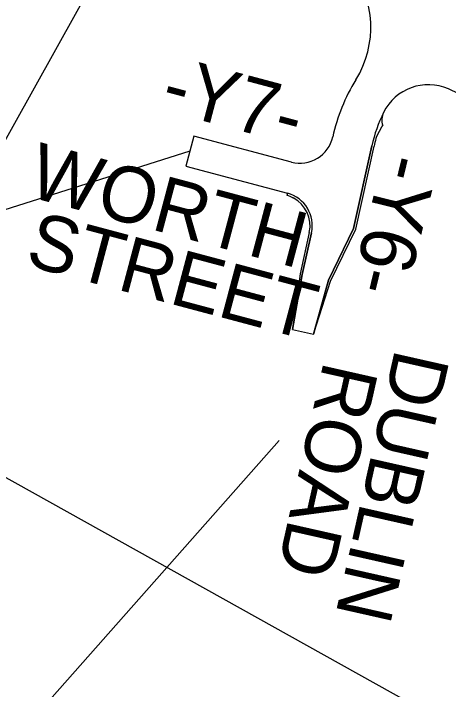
# Model space of a CAD drawing. Extents: x 1754939 to 1770240, y 706534 to 717510.
# Drawn here: x 1763770 to 1764161, y 710711 to 711317 of the extents above; entities that cross this region are included whole.
import ezdxf

# ---------------------------------------------------------------- set-up
doc = ezdxf.new("R2010")
doc.units = 0
for name, color, linetype in [('ENG SEALS CELL', 7, 'Continuous'), ('Prop Lane Arrow CELL', 7, 'Continuous'), ('Prop SS Cut Line', 7, 'Continuous'), ('Sheet PE Seal Cell', 7, 'Continuous')]:
    doc.layers.add(name, color=color, linetype=linetype)

msp = doc.modelspace()

# ---------------------------------------------------------------- linework, layer by layer
at = {"layer": 'ENG SEALS CELL'}
msp.add_lwpolyline([(1763634.1949825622, 710972.3161103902), (1763634.1949825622, 710972.3161103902), (1763865.6585117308, 711387.9613402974), (1764374.3315787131, 711761.9610198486), (1765360.9096948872, 711212.5534788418), (1765258.0264943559, 711027.8033728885), (1764850.0689356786, 710295.2231090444)], close=True, dxfattribs=at)
at = {"layer": 'Prop Lane Arrow CELL'}
for p, q in [((1764101.5980315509, 711216.4287330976), (1764101.5965902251, 711216.4250910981)), ((1764101.5965902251, 711216.4250910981), (1764101.5980315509, 711216.4287330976)), ((1763931.965230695, 711206.8954704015), (1763924.7579165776, 711179.8389624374)), ((1764019.687593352, 711183.5279824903), (1763931.965230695, 711206.8954704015)), ((1764075.378798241, 711123.8104545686), (1764091.8260664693, 711198.1455051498)), ((1764091.8260664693, 711198.1455051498), (1764075.378798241, 711123.8104545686)), ((1764077.3315700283, 711123.378387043), (1764093.7788382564, 711197.7134376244)), ((1763924.7579165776, 711179.8389624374), (1764016.1035829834, 711155.5062986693)), ((1764016.1035829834, 711155.5062986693), (1764015.6711234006, 711153.5517549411)), ((1764035.7202657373, 711120.4682376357), (1764027.4744461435, 711083.2004428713)), ((1764037.6730375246, 711120.0361701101), (1764029.4272179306, 711082.7683753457)), ((1764029.4272179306, 711082.7683753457), (1764037.6730375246, 711120.0361701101)), ((1764052.8604793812, 711077.5835650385), (1764075.378798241, 711123.8104545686)), ((1764075.378798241, 711123.8104545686), (1764052.8604793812, 711077.5835650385)), ((1764054.7175302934, 711076.829219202), (1764077.3315700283, 711123.378387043)), ((1764029.4272179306, 711082.7683753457), (1764020.6076975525, 711033.5105090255)), ((1764027.4744461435, 711083.2004428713), (1764023.234030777, 711052.5154751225)), ((1764025.2290656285, 711059.3212925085), (1764029.4272179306, 711082.7683753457)), ((1764039.580459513, 711029.3126225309), (1764052.8604793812, 711077.5835650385)), ((1764052.8604793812, 711077.5835650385), (1764039.7858838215, 711030.0593100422)), ((1764039.791703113, 711029.9757347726), (1764054.7175302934, 711076.829219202)), ((1764020.6076975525, 711033.5105090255), (1764025.2290656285, 711059.3212925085)), ((1764025.2290656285, 711059.3212925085), (1764024.136629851, 711055.4423247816)), ((1764024.136629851, 711055.4423247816), (1764025.2290656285, 711059.3212925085)), ((1764023.234030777, 711052.5154751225), (1764020.6076975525, 711033.5105090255)), ((1764024.136629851, 711055.4423247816), (1764023.234030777, 711052.5154751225)), ((1764023.234030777, 711052.5154751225), (1764024.136629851, 711055.4423247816)), ((1764020.6076975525, 711033.5105090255), (1764039.580459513, 711029.3126225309)), ((1764039.7858838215, 711030.0593100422), (1764039.580459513, 711029.3126225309)), ((1764039.580459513, 711029.3126225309), (1764039.791703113, 711029.9757347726)), ((1764039.791703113, 711029.9757347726), (1764039.7858838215, 711030.0593100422)), ((1764039.7858838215, 711030.0593100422), (1764039.791703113, 711029.9757347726))]:
    msp.add_line(p, q, dxfattribs=at)
msp.add_lwpolyline([(1764020.9883800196, 711151.5184946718), (1764021.0888121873, 711151.4804514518), (1764021.301786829, 711151.3579795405)], dxfattribs=at)
for centre, radius, start, end in [((1764000.948892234, 711304.5823502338), 90.00000000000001, 328.2998706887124, 36.9925322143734), ((1764218.756232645, 711170.0611159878), 166.00000000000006, 148.29987068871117, 167.48987396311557), ((1764142.6521907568, 711207.9184112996), 45.00000000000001, 66.45710526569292, 153.55234991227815), ((1764088.7283958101, 711084.1556368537), 180.00000000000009, 57.82781423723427, 66.45710526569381), ((1764218.756232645, 711170.0611159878), 129.99999999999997, 153.55234991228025, 167.52381704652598), ((1764218.756232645, 711170.0611159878), 130.00000000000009, 153.55234991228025, 167.52381704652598), ((1764115.7919406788, 711221.2798096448), 15.000000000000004, 153.55234991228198, 198.86897661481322), ((1764027.4097156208, 711212.517098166), 30.00000000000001, 255.08391524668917, 347.48987396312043), ((1764218.756232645, 711170.0611159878), 128.00000000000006, 164.3624517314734, 167.52381704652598), ((1764008.3814607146, 711126.5171829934), 30.000000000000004, 347.52381704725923, 75.0839152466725), ((1764008.3814607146, 711126.5171829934), 30.000000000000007, 347.52381704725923, 75.0839152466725), ((1764008.3814607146, 711126.5171829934), 28.000000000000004, 63.24046010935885, 74.90953166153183), ((1764008.3814607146, 711126.5171829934), 28.000000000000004, 347.52381704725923, 62.519918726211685)]:
    msp.add_arc(centre, radius, start, end, dxfattribs=at)
for points in [[(1764098.387763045, 711210.5754229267), (1764098.482146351, 711210.7585364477), (1764098.6064961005, 711210.998668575), (1764098.7313236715, 711211.2384575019), (1764098.8566281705, 711211.4779022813), (1764098.9824087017, 711211.7170019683), (1764099.1086643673, 711211.9557556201), (1764099.2353942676, 711212.1941622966), (1764099.3625975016, 711212.4322210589), (1764099.4902731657, 711212.6699309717), (1764099.6184203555, 711212.907291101), (1764099.7470381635, 711213.1443005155), (1764099.876125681, 711213.3809582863), (1764100.0056819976, 711213.617263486), (1764100.1357062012, 711213.8532151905), (1764100.2661973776, 711214.0888124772), (1764100.39715461, 711214.3240544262), (1764100.5285769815, 711214.5589401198), (1764100.6604635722, 711214.7934686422), (1764100.7928134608, 711215.0276390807), (1764100.925625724, 711215.2614505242), (1764101.058899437, 711215.4949020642), (1764101.192633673, 711215.7279927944), (1764101.3268275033, 711215.9607218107), (1764101.461479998, 711216.1930882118), (1764101.5965902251, 711216.4250910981)], [(1764095.4940085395, 711204.5636392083), (1764095.5312704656, 711204.6465091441), (1764095.643389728, 711204.8949069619), (1764095.7560085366, 711205.142985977), (1764095.869126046, 711205.390745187), (1764095.9827414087, 711205.6381835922), (1764096.0968537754, 711205.8853001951), (1764096.2114622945, 711206.1320939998), (1764096.326566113, 711206.378564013), (1764096.4421643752, 711206.6247092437), (1764096.5582562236, 711206.8705287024), (1764096.6748407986, 711207.1160214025), (1764096.7919172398, 711207.3611863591), (1764096.9094846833, 711207.6060225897), (1764097.0275422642, 711207.850529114), (1764097.146089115, 711208.0947049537), (1764097.2651243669, 711208.3385491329), (1764097.3846471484, 711208.5820606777), (1764097.5046565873, 711208.8252386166), (1764097.625151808, 711209.06808198), (1764097.7461319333, 711209.3105898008), (1764097.8675960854, 711209.5527611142), (1764097.9895433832, 711209.7945949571), (1764098.1119729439, 711210.0360903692), (1764098.2348838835, 711210.277246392), (1764098.358275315, 711210.5180620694), (1764098.387763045, 711210.5754229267)]]:
    msp.add_spline(points, degree=3, dxfattribs=at)
at = {"layer": 'Prop SS Cut Line'}
for p, q in [((1763928.3615736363, 711193.3672164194), (1763437.1754715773, 711037.1977477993)), ((1764008.7387842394, 710933.7180861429), (1763671.249473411, 710553.0539477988))]:
    msp.add_line(p, q, dxfattribs=at)

# ---------------------------------------------------------------- texts
at = {"layer": 'Sheet PE Seal Cell'}
for s, height, rotation, p in [('-Y7-', 49.999999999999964, 345.0839152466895, (1763900.6590760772, 711230.9803079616)), ('WORTH ', 50, 345.0839152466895, (1763781.2340582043, 711153.1184858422)), ('-Y6-', 49.999999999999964, 256.1124162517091, (1764103.310471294, 711193.6319183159)), ('STREET', 50, 345.0839152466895, (1763779.3693110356, 711091.5229472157)), ('DUBLIN ', 50, 257.3118059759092, (1764112.9898885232, 711017.3548929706)), ('ROAD', 50, 257.3118059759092, (1764048.9989129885, 711006.2993145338))]:
    msp.add_text(s, height=height, rotation=rotation, dxfattribs=at).set_placement(p)

doc.saveas('drawing.dxf')
